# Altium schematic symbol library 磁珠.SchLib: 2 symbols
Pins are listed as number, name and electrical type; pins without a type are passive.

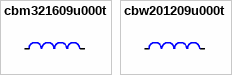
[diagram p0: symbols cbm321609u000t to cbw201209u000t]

## cbm321609u000t
designator BEAD??  (value not drawn)
阻抗@频率:0Ω@100MHz;直流电阻(DCR):10mΩ;; Manufacturer: FH(风华); AddInBom: yes; ModelId: 85bdab7b3d4c4074b81d208eb5e865b3; ModelName: L1206_L3.2-W1.6-H1.1; ModelTransform: 125.984,62.835,0,0,0,0,0,0,0; DC Resistance(DCR): 10mΩ; Current Rating: 6A; Number of Circuits: 1
footprint L1206
pins: 1, 2

## cbw201209u000t
designator L??  (value not drawn)
阻抗@频率:0Ω@100MHz;直流电阻(DCR):20mΩ;; Manufacturer: FH(风华); AddInBom: yes; ModelId: 37a81e68749a4138bd2dfa6897b24b85; ModelName: R0805_L2.0-W1.3-H0.6; ModelTransform: 78.74,51.181,0,0,0,0,0,0.001,0; DC Resistance(DCR): 20mΩ; Current Rating: 3A; Number of Circuits: 1
footprint L0805
pins: 1, 2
